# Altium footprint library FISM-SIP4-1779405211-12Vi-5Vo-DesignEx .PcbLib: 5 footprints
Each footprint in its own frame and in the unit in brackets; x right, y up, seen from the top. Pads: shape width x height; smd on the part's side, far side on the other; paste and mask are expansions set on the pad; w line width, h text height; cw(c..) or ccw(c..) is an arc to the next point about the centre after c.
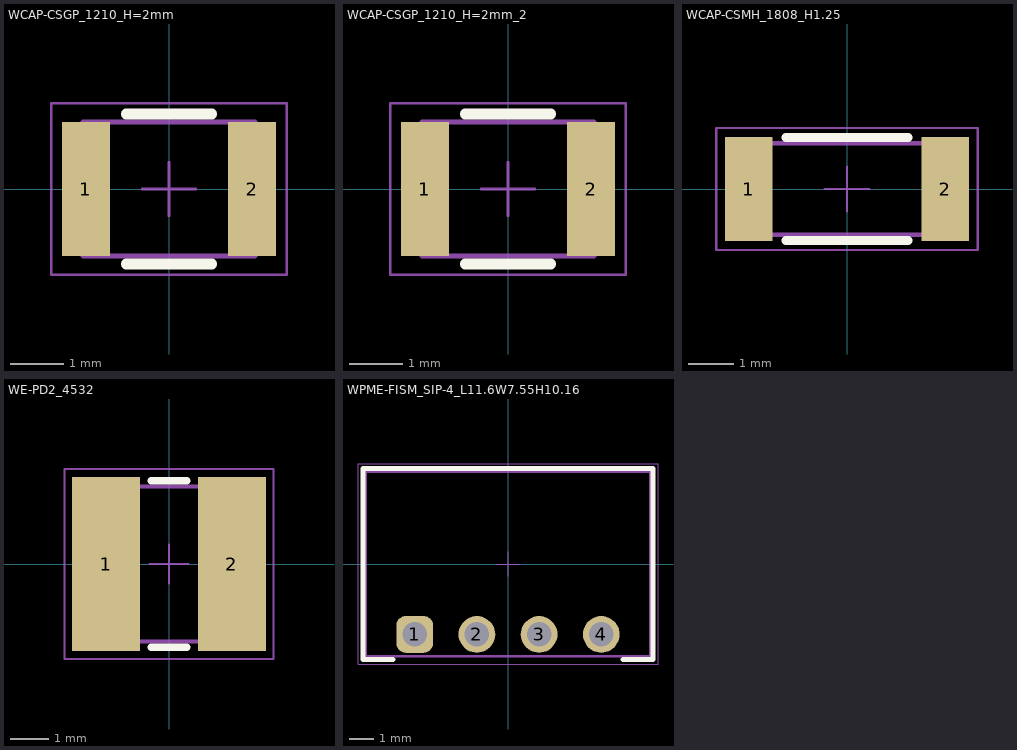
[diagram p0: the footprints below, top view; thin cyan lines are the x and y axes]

## WCAP-CSGP_1210_H=2mm [mm] "Ceramic Capacitors, body 3.2x2.5mm"
height 2.2
pads (2):
  rect 0.9x2.5 smd: 1(-1.55,0) 2(1.55,0)
Top Overlay:
  lines w0.2: -0.8,-1.4 0.8,-1.4 ; -0.8,1.4 0.8,1.4
Top Assembly:
  lines w0.1: -1.6,-1.25 1.6,-1.25 1.6,1.25 -1.6,1.25 -1.6,-1.25
  text ".Designator" at -1.4,-0.6 h1.2
Top 3D Body:
  lines w0.1: -1.6,-1.25 -1.6,1.25 1.6,1.25 1.6,-1.25 -1.6,-1.25
Top Courtyard:
  lines w0.05: -0.5,0 0.5,0 ; 0,-0.5 0,0.5 ; -2.2,-1.6 2.2,-1.6 2.2,1.6 -2.2,1.6 -2.2,-1.6
3D body "3.2x2.5x2x0.75.stp": height 2, standoff 0, extent -1.6,-1.25 1.6,1.25

## WCAP-CSGP_1210_H=2mm_2 [mm]
pads (2):
  rect 0.9x2.5 smd: 1(-1.55,0) 2(1.55,0)
Top Overlay:
  lines w0.2: -0.8,-1.4 0.8,-1.4 ; -0.8,1.4 0.8,1.4
Top Assembly:
  lines w0.1: -1.6,-1.25 -1.6,1.25 1.6,1.25 1.6,-1.25 -1.6,-1.25
  text ".Designator" at -1.4,-0.6 h1.2
Top 3D Body:
  lines w0.1: -1.6,-1.25 1.6,-1.25 1.6,1.25 -1.6,1.25 -1.6,-1.25
Top Courtyard:
  lines w0.05: -0.5,0 0.5,0 ; 0,-0.5 0,0.5 ; -2.2,-1.6 -2.2,1.6 2.2,1.6 2.2,-1.6 -2.2,-1.6
3D body "3.2x2.5x2x0.75.stp": height 2, standoff 0, extent -1.6,-1.25 1.6,1.25

## WCAP-CSMH_1808_H1.25 [mm] "Ceramic Capacitors, body 4.5x2.03mm"
height 1.25
pads (2):
  rect 1.05x2.3 smd: 1(-2.175,0) 2(2.175,0)
Top Overlay:
  lines w0.2: -1.35,-1.14 1.35,-1.14 ; -1.35,1.14 1.35,1.14
Top 3D Body:
  lines w0.1: -2.25,-1.015 2.25,-1.015 2.25,1.015 -2.25,1.015 -2.25,-1.015
Top Courtyard:
  lines w0.05: -0.5,0 0.5,0 ; 0,-0.5 0,0.5 ; -2.9,-1.35 -2.9,1.35 2.9,1.35 2.9,-1.35 -2.9,-1.35
3D body "4.5x2.03x1.25x0.5.stp": height 1.25, standoff 0, extent -2.25,-1.015 2.25,1.015

## WE-PD2_4532 [mm] "SMD Power Inductor, 2-Leads, body 4x4.5mm"
height 3.2
pads (2):
  rect 1.75x4.5 smd: 1(-1.625,0) 2(1.625,0)
Top Overlay:
  lines w0.2: -0.45,-2.15 0.45,-2.15 ; -0.45,2.15 0.45,2.15
Top Assembly:
  lines w0.1: -2.25,-2 2.25,-2 2.25,2 -2.25,2 -2.25,-2
Top 3D Body:
  lines w0.1: -2.25,-2 2.25,-2 2.25,2 -2.25,2 -2.25,-2
Top Courtyard:
  lines w0.05: -0.5,0 0.5,0 ; 0,-0.5 0,0.5 ; -2.7,-2.45 -2.7,2.45 2.7,2.45 2.7,-2.45 -2.7,-2.45
3D body "744773xxx.stp": height 3.22, standoff 0.02, extent -2.25,-2 2.25,2

## WPME-FISM_SIP-4_L11.6W7.55H10.16 [mm] "Power Module, SIP-4, body 11.60x7.55mm"
height 10.41
pads (4):
  rrect50% 1.5x1.5 hole 1 paste-0.1: 1(-3.81,-2.875)
  round 1.5 hole 1 paste-0.1: 2(-1.27,-2.875) 3(1.27,-2.875) 4(3.81,-2.875)
Top Overlay:
  lines w0.2: -4.7,-3.9 -5.925,-3.9 -5.925,3.9 5.925,3.9 5.925,-3.9 4.7,-3.9
Top Assembly:
  lines w0.1: -5.8,-3.775 -5.8,3.775 5.8,3.775 5.8,-3.775 -5.8,-3.775
  text ".Designator" at -7.498,-0.5 h1.5
Top 3D Body:
  lines w0.1: -5.8,-3.775 -5.8,3.775 5.8,3.775 5.8,-3.775 -5.8,-3.775
Top Courtyard:
  lines w0.05: -0.5,0 0.5,0 ; 0,-0.5 0,0.5 ; -6.125,-4.1 -6.125,4.1 6.125,4.1 6.125,-4.1 -6.125,-4.1
3D body "1779405111.stp": height 10.16, standoff -4.1, extent -5.8,-3.775 5.8,3.775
